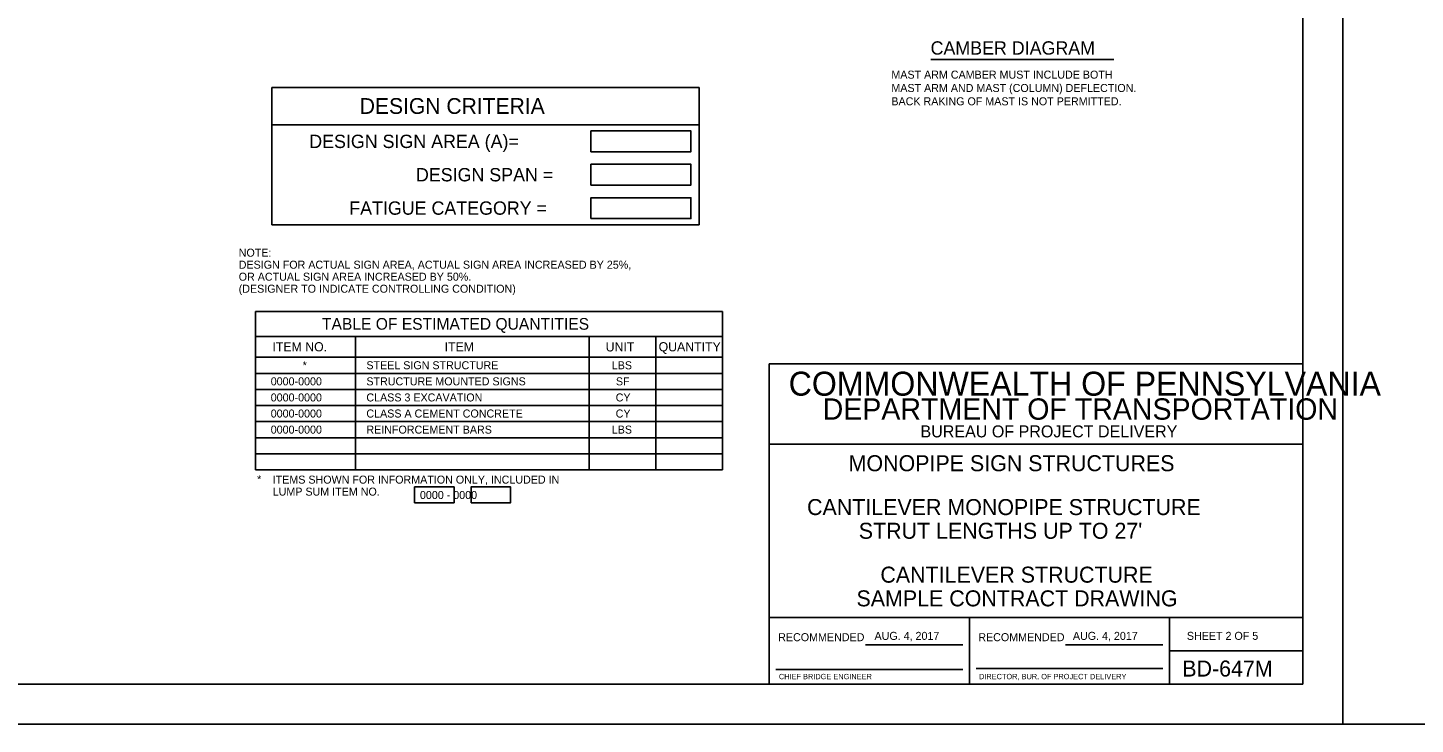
# Model space of a CAD drawing. Extents: x 640117 to 642655, y 297247 to 298435.
# Drawn here: x 640466 to 640986, y 297247 to 297508 of the extents above; entities that cross this region are included whole.
import ezdxf

# ---------------------------------------------------------------- set-up
doc = ezdxf.new("R2010")
doc.units = 0
for name, color, linetype in [('1', 7, 'Continuous'), ('10', 7, 'Continuous'), ('17', 7, 'Continuous'), ('2', 7, 'Continuous'), ('30', 7, 'Continuous'), ('52', 7, 'Continuous'), ('53', 7, 'Continuous'), ('PLT-BNDY', 7, 'Continuous')]:
    doc.layers.add(name, color=color, linetype=linetype)

msp = doc.modelspace()

# ---------------------------------------------------------------- linework, layer by layer
at = {"layer": '1'}
for p, q in [((640818.46, 297262.46), (640818.46, 297287.46)), ((640779.54, 297277.17), (640815.96, 297277.17)), ((640854.54, 297277.17), (640890.96, 297277.17)), ((640745.96, 297267.96), (640815.96, 297267.96)), ((640820.96, 297268.33), (640890.96, 297268.33))]:
    msp.add_line(p, q, dxfattribs=at)
at = {"layer": '10'}
for points in [[(640676.57, 297461.98), (640714.07, 297461.98), (640714.07, 297469.79), (640676.57, 297469.79)], [(640676.57, 297449.48), (640714.07, 297449.48), (640714.07, 297457.29), (640676.57, 297457.29)], [(640676.57, 297436.98), (640714.07, 297436.98), (640714.07, 297444.79), (640676.57, 297444.79)], [(640610.48, 297330.43), (640625.3, 297330.43), (640625.3, 297336.4), (640610.48, 297336.4)], [(640631.68, 297330.43), (640646.5, 297330.43), (640646.5, 297336.4), (640631.68, 297336.4)]]:
    msp.add_lwpolyline(points, close=True, dxfattribs=at)
at = {"layer": '17'}
for p, q in [((640717.2, 297486.13), (640557.01, 297486.13)), ((640557.01, 297486.13), (640557.01, 297434.63)), ((640717.2, 297486.13), (640717.2, 297434.63)), ((640557.01, 297472.13), (640717.2, 297472.13)), ((640557.01, 297434.63), (640717.2, 297434.63)), ((640550.88, 297402.18), (640550.88, 297342.79)), ((640725.88, 297402.17), (640550.88, 297402.18)), ((640725.88, 297402.17), (640725.88, 297342.79)), ((640725.88, 297392.8), (640550.88, 297392.81)), ((640588.38, 297392.8), (640588.38, 297342.79)), ((640675.88, 297392.8), (640675.88, 297342.8)), ((640700.88, 297392.8), (640700.88, 297342.8)), ((640725.88, 297384.99), (640550.88, 297384.99)), ((640725.88, 297378.96), (640550.88, 297378.96)), ((640725.88, 297372.93), (640550.88, 297372.94)), ((640725.88, 297366.9), (640550.88, 297366.91)), ((640725.88, 297360.87), (640550.88, 297360.88)), ((640725.88, 297354.85), (640550.88, 297354.85)), ((640725.88, 297348.82), (640550.88, 297348.82)), ((640725.88, 297342.79), (640550.88, 297342.79))]:
    msp.add_line(p, q, dxfattribs=at)
at = {"layer": '2'}
for p, q in [((640943.46, 297826.46), (640943.46, 297262.46)), ((640943.46, 297382.46), (640743.46, 297382.46)), ((640743.46, 297382.46), (640743.46, 297262.46)), ((640943.46, 297262.46), (640943.46, 297382.46)), ((640943.46, 297352.46), (640743.46, 297352.46)), ((640943.46, 297287.46), (640743.46, 297287.46)), ((640893.46, 297287.46), (640893.46, 297262.46)), ((640893.46, 297274.96), (640943.46, 297274.96)), ((640943.46, 297262.46), (640157.46, 297262.46)), ((640743.46, 297262.46), (640943.46, 297262.46))]:
    msp.add_line(p, q, dxfattribs=at)
at = {"layer": '30'}
msp.add_line((640803.94, 297496.6), (640872.54, 297496.6), dxfattribs=at)
at = {"layer": 'PLT-BNDY'}
for points in [[(640117.46, 297841.46), (640958.46, 297841.46), (640958.46, 297247.46), (640117.46, 297247.46)], [(640958.46, 297841.46), (641799.46, 297841.46), (641799.46, 297247.46), (640958.46, 297247.46)]]:
    msp.add_lwpolyline(points, close=True, dxfattribs=at)

# ---------------------------------------------------------------- texts
at = {"layer": '1'}
for s, height, p in [('RECOMMENDED', 3, (640746.79, 297278.58)), ('RECOMMENDED', 3, (640821.79, 297278.58)), ('CHIEF BRIDGE ENGINEER', 2.0002, (640747.05, 297264.33)), ('DIRECTOR, BUR. OF PROJECT DELIVERY', 2.0002, (640822.06, 297264.33))]:
    msp.add_text(s, height=height, dxfattribs=at).set_placement(p)
at = {"layer": '10'}
for s, p in [('MONOPIPE SIGN STRUCTURES', (640773.18, 297342.28)), ('CANTILEVER MONOPIPE STRUCTURE', (640757.61, 297325.84)), ("STRUT LENGTHS UP TO 27'", (640776.98, 297316.96)), ('CANTILEVER STRUCTURE', (640785.09, 297300.51)), ('SAMPLE CONTRACT DRAWING', (640776.13, 297291.63)), ('BD-647M', (640898.25, 297265.33))]:
    msp.add_text(s, height=6, dxfattribs=at).set_placement(p)
at = {"layer": '2'}
for s, height, p in [('CAMBER DIAGRAM', 4.9969, (640803.91, 297498.39)), ('DESIGN CRITERIA', 5.9062, (640589.95, 297476.19)), ('DESIGN SIGN AREA (A)=', 5, (640571.01, 297463.39)), ('DESIGN SPAN =', 5, (640611.01, 297450.89)), ('FATIGUE CATEGORY =', 5, (640586.01, 297438.39)), ('NOTE:', 3, (640544.58, 297422.67)), ('DESIGN FOR ACTUAL SIGN AREA, ACTUAL SIGN AREA INCREASED BY 25%,', 3, (640544.58, 297418.17)), ('OR ACTUAL SIGN AREA INCREASED BY 50%.', 3, (640544.58, 297413.67)), ('(DESIGNER TO INDICATE CONTROLLING CONDITION)', 3, (640544.58, 297409.17)), ('TABLE OF ESTIMATED QUANTITIES', 4.375, (640575.79, 297395.31)), ('ITEM NO.', 3.445, (640557.23, 297387.19)), ('ITEM', 3.445, (640621.74, 297387.19)), ('UNIT', 3.445, (640682.13, 297387.17)), ('QUANTITY', 3.445, (640701.97, 297387.19)), ('*', 3, (640568.55, 297380.49)), ('STEEL SIGN STRUCTURE', 3, (640592.43, 297380.49)), ('LBS', 3, (640684.41, 297380.48)), ('0000-0000', 3, (640556.58, 297374.46)), ('STRUCTURE MOUNTED SIGNS', 3, (640592.43, 297374.46)), ('SF', 3, (640685.96, 297374.45)), ('COMMONWEALTH OF PENNSYLVANIA', 9, (640750.71, 297370.58)), ('0000-0000', 3, (640556.58, 297368.43)), ('CLASS 3 EXCAVATION', 3, (640592.43, 297368.43)), ('CY', 3, (640685.88, 297368.43)), ('DEPARTMENT OF TRANSPORTATION', 8.0002, (640763.46, 297361.58)), ('0000-0000', 3, (640556.58, 297362.4)), ('CLASS A CEMENT CONCRETE', 3, (640592.43, 297362.4)), ('CY', 3, (640685.88, 297362.4)), ('0000-0000', 3, (640556.58, 297356.37)), ('REINFORCEMENT BARS', 3, (640592.43, 297356.37)), ('LBS', 3, (640684.41, 297356.37)), ('BUREAU OF PROJECT DELIVERY', 4.5, (640800.12, 297354.96)), ('*', 3, (640551.47, 297337.79)), ('ITEMS SHOWN FOR INFORMATION ONLY, INCLUDED IN', 3, (640557.32, 297337.63)), ('LUMP SUM ITEM NO. ', 3, (640557.32, 297333.13)), ('0000 - 0000', 3, (640612.51, 297331.87)), ('SHEET 2 OF 5', 3, (640899.97, 297279.08))]:
    msp.add_text(s, height=height, dxfattribs=at).set_placement(p)
at = {"layer": '52'}
for p in [(640782.89, 297279.07), (640857.25, 297279.07)]:
    msp.add_text('AUG. 4, 2017', height=3, dxfattribs=at).set_placement(p)
at = {"layer": '53'}
for s, p in [('MAST ARM CAMBER MUST INCLUDE BOTH', (640789.21, 297489.4)), ('MAST ARM AND MAST (COLUMN) DEFLECTION.  ', (640789.21, 297484.4)), ('BACK RAKING OF MAST IS NOT PERMITTED.', (640789.21, 297479.4))]:
    msp.add_text(s, height=3, dxfattribs=at).set_placement(p)

doc.saveas('drawing.dxf')
